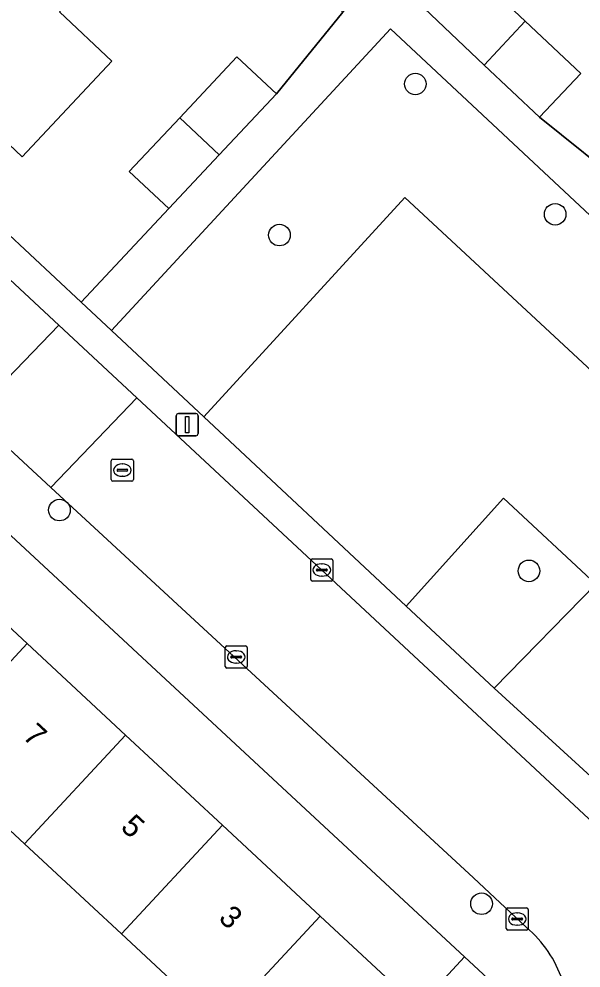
# Model space of a CAD drawing. Extents: x 159217 to 160349, y 381246 to 382172.
# Drawn here: x 159794.16 to 159819.61, y 381597.04 to 381640.02 of the extents above; entities that cross this region are included whole.
import ezdxf

# ---------------------------------------------------------------- set-up
doc = ezdxf.new("R2010")
doc.units = 0
for name, color, linetype in [('IMGEO_Boom', 7, 'Continuous'), ('IMGEO_Erf', 7, 'Continuous'), ('IMGEO_Groenvoorziening', 7, 'Continuous'), ('IMGEO_Kolk', 7, 'Continuous'), ('IMGEO_Lichtmast', 7, 'Continuous'), ('IMGEO_Pand', 7, 'Continuous'), ('IMGEO_Pand_nummerreeks', 7, 'Continuous'), ('IMGEO_Rijbaan_lokaal_open', 7, 'Continuous'), ('IMGEO_Rioolput', 7, 'Continuous'), ('IMGEO_Voetpad_open', 7, 'Continuous')]:
    doc.layers.add(name, color=color, linetype=linetype)

msp = doc.modelspace()

# ---------------------------------------------------------------- linework, layer by layer
at = {"layer": 'IMGEO_Boom'}
for centre in [(159812.109, 381637.076), (159818.442, 381631.175), (159805.956, 381630.234), (159795.992, 381617.781), (159817.255, 381615.027), (159815.108, 381599.955)]:
    msp.add_circle(centre, 0.489, dxfattribs=at)
at = {"layer": 'IMGEO_Erf'}
msp.add_lwpolyline([(159803.656, 381658.338), (159807.515, 381662.454), (159807.241, 381662.71), (159807.449, 381662.932), (159812.834, 381657.884), (159812.651, 381657.689), (159812.448, 381657.879), (159808.564, 381653.736), (159804.32, 381649.211), (159800.254, 381644.874), (159796.153, 381640.501), (159795.998, 381640.336), (159798.369, 381638.113), (159794.311, 381633.784), (159792.204, 381635.759), (159786.767, 381640.857), (159786.941, 381641.042), (159787.205, 381640.794), (159791.245, 381645.103), (159795.346, 381649.477), (159799.412, 381653.813)], close=True, dxfattribs=at)
for points in [[(159780.684, 381642.43), (159796.971, 381627.201), (159800.946, 381631.43), (159799.157, 381633.108), (159801.44, 381635.543), (159804.025, 381638.3), (159805.815, 381636.622), (159808.819, 381640.327), (159806.825, 381642.15), (159809.145, 381644.687), (159811.789, 381647.578), (159813.783, 381645.754), (159811.116, 381642.838), (159810.61, 381642.285), (159812.503, 381640.514), (159814.366, 381642.487), (159817.086, 381639.917), (159819.598, 381637.544), (159817.734, 381635.572), (159821.799, 381632.312)], [(159812.344, 381595.399), (159814.342, 381597.549), (159774.325, 381634.697), (159774.102, 381634.87), (159773.865, 381635.022), (159773.615, 381635.152), (159773.355, 381635.259), (159773.086, 381635.343), (159772.811, 381635.402), (159772.531, 381635.436), (159772.249, 381635.446), (159771.968, 381635.43), (159771.689, 381635.389), (159771.416, 381635.323), (159771.149, 381635.234), (159770.891, 381635.12), (159770.644, 381634.984), (159770.41, 381634.827), (159770.255, 381634.704), (159745.629, 381606.638), (159764.873, 381588.845)], [(159803.227, 381594.477), (159798.802, 381598.589), (159794.41, 381602.671), (159789.957, 381606.81), (159785.693, 381610.772), (159785.453, 381610.514), (159785.255, 381610.698), (159786.948, 381612.519), (159790.351, 381616.181), (159790.548, 381615.997), (159790.268, 381615.695), (159794.532, 381611.733), (159798.985, 381607.593), (159803.377, 381603.512), (159807.802, 381599.4), (159812.029, 381595.471)]]:
    msp.add_lwpolyline(points, dxfattribs=at)
at = {"layer": 'IMGEO_Groenvoorziening'}
for points in [[(159831.37, 381620.522), (159810.981, 381639.573), (159798.344, 381625.917), (159802.529, 381622.003), (159811.633, 381631.939), (159833.028, 381612.068), (159836.458, 381615.77)], [(159811.633, 381631.939), (159802.529, 381622.003), (159811.692, 381613.435), (159816.102, 381618.314), (159820.288, 381614.431), (159815.676, 381609.71), (159820.934, 381604.918), (159825.276, 381609.576), (159828.247, 381606.909), (159833.028, 381612.068)], [(159811.692, 381613.435), (159815.676, 381609.71), (159820.288, 381614.431), (159816.102, 381618.314)]]:
    msp.add_lwpolyline(points, close=True, dxfattribs=at)
msp.add_lwpolyline([(159815.605, 381596.377), (159814.342, 381597.549), (159812.344, 381595.399), (159807.391, 381590.069), (159807.261, 381590.19), (159803.375, 381586.01), (159800.881, 381583.327), (159799.047, 381585.03), (159797.402, 381586.508), (159796.068, 381585.081), (159795.325, 381583.417), (159801.486, 381577.736), (159815.991, 381593.468)], dxfattribs=at)
at = {"layer": 'IMGEO_Kolk'}
for p, q in [((159807.374, 381614.642), (159807.374, 381615.494)), ((159807.449, 381615.568), (159808.301, 381615.568)), ((159808.375, 381615.494), (159808.375, 381614.642)), ((159807.633, 381615.062), (159807.633, 381615.074)), ((159807.676, 381615.111), (159808.074, 381615.111)), ((159807.862, 381615.348), (159807.887, 381615.348)), ((159808.117, 381615.074), (159808.117, 381615.062)), ((159808.071, 381615.025), (159807.673, 381615.025)), ((159807.885, 381614.788), (159807.86, 381614.788)), ((159808.301, 381614.568), (159807.449, 381614.568)), ((159803.573, 381611.63), (159804.425, 381611.63)), ((159803.498, 381610.704), (159803.498, 381611.556)), ((159803.8, 381611.173), (159804.198, 381611.173)), ((159803.986, 381611.41), (159804.011, 381611.41)), ((159804.499, 381611.556), (159804.499, 381610.704)), ((159803.757, 381611.124), (159803.757, 381611.136)), ((159804.195, 381611.087), (159803.797, 381611.087)), ((159804.009, 381610.85), (159803.984, 381610.85)), ((159804.241, 381611.136), (159804.241, 381611.124)), ((159804.425, 381610.63), (159803.573, 381610.63)), ((159816.224, 381598.838), (159816.224, 381599.69)), ((159816.299, 381599.764), (159817.151, 381599.764)), ((159817.225, 381599.69), (159817.225, 381598.838)), ((159816.483, 381599.258), (159816.483, 381599.27)), ((159816.921, 381599.221), (159816.523, 381599.221)), ((159816.526, 381599.307), (159816.924, 381599.307)), ((159816.712, 381599.544), (159816.737, 381599.544)), ((159816.967, 381599.27), (159816.967, 381599.258)), ((159817.151, 381598.764), (159816.299, 381598.764)), ((159816.735, 381598.984), (159816.71, 381598.984))]:
    msp.add_line(p, q, dxfattribs=at)
for points in [[(159807.374, 381614.642), (159807.374, 381615.494)], [(159807.449, 381615.568), (159808.301, 381615.568)], [(159808.375, 381615.494), (159808.375, 381614.642)], [(159808.301, 381614.568), (159807.449, 381614.568)], [(159803.573, 381611.63), (159804.425, 381611.63)], [(159803.498, 381610.704), (159803.498, 381611.556)], [(159804.499, 381611.556), (159804.499, 381610.704)], [(159804.425, 381610.63), (159803.573, 381610.63)], [(159816.224, 381598.838), (159816.224, 381599.69)], [(159816.299, 381599.764), (159817.151, 381599.764)], [(159817.225, 381599.69), (159817.225, 381598.838)], [(159817.151, 381598.764), (159816.299, 381598.764)]]:
    msp.add_lwpolyline(points, dxfattribs=at)
for centre, radius, start, end in [((159807.451, 381615.492), 0.0765, 91.552, 178.448), ((159807.451, 381615.492), 0.0765, 91.552, 178.448), ((159808.299, 381615.492), 0.0765, 1.552, 88.448), ((159808.299, 381615.492), 0.0765, 1.552, 88.448), ((159807.673, 381615.071), 0.0403, 85.8775, 175.7526), ((159807.67, 381615.061), 0.0366, 178.938, 274.7102), ((159808.074, 381615.068), 0.043, 264.8664, 352.4533), ((159808.078, 381615.073), 0.0386, 1.7309, 96.639), ((159807.451, 381614.644), 0.0765, 181.552, 268.448), ((159807.451, 381614.644), 0.0765, 181.552, 268.448), ((159808.299, 381614.644), 0.0765, 271.552, 358.448), ((159808.299, 381614.644), 0.0765, 271.552, 358.448), ((159803.575, 381611.554), 0.0765, 91.552, 178.448), ((159803.575, 381611.554), 0.0765, 91.552, 178.448), ((159804.423, 381611.554), 0.0765, 1.552, 88.448), ((159804.423, 381611.554), 0.0765, 1.552, 88.448), ((159803.797, 381611.133), 0.0403, 85.8775, 175.7526), ((159804.202, 381611.135), 0.0386, 1.7309, 96.639), ((159803.794, 381611.123), 0.0366, 178.938, 274.7102), ((159804.198, 381611.13), 0.043, 264.8664, 352.4533), ((159803.575, 381610.706), 0.0765, 181.552, 268.448), ((159803.575, 381610.706), 0.0765, 181.552, 268.448), ((159804.423, 381610.706), 0.0765, 271.552, 358.448), ((159804.423, 381610.706), 0.0765, 271.552, 358.448), ((159816.301, 381599.688), 0.0765, 91.552, 178.448), ((159816.301, 381599.688), 0.0765, 91.552, 178.448), ((159817.149, 381599.688), 0.0765, 1.552, 88.448), ((159817.149, 381599.688), 0.0765, 1.552, 88.448), ((159816.523, 381599.267), 0.0403, 85.8775, 175.7526), ((159816.52, 381599.257), 0.0366, 178.938, 274.7102), ((159816.924, 381599.264), 0.043, 264.8664, 352.4533), ((159816.928, 381599.269), 0.0386, 1.7309, 96.639), ((159816.301, 381598.84), 0.0765, 181.552, 268.448), ((159816.301, 381598.84), 0.0765, 181.552, 268.448), ((159817.149, 381598.84), 0.0765, 271.552, 358.448), ((159817.149, 381598.84), 0.0765, 271.552, 358.448)]:
    msp.add_arc(centre, radius, start, end, dxfattribs=at)
for centre, major_axis, ratio, start_param, end_param in [((159807.861, 381615.068), (-0.387, 0.002), 0.722429, 4.712389, 7.853982), ((159807.886, 381615.068), (-0.39, 0.002), 0.717154, 1.570796, 4.712389), ((159803.985, 381611.13), (-0.387, 0.002), 0.722429, 4.712389, 7.853982), ((159804.01, 381611.13), (-0.39, 0.002), 0.717154, 1.570796, 4.712389), ((159816.711, 381599.264), (-0.387, 0.002), 0.722429, 4.712389, 7.853982), ((159816.736, 381599.264), (-0.39, 0.002), 0.717154, 1.570796, 4.712389)]:
    msp.add_ellipse(centre, major_axis=major_axis, ratio=ratio, start_param=start_param, end_param=end_param, dxfattribs=at)
at = {"layer": 'IMGEO_Lichtmast'}
for p, q in [((159801.285, 381621.25), (159801.285, 381622.05)), ((159801.285, 381622.05), (159801.285, 381621.25)), ((159801.385, 381622.15), (159802.175, 381622.15)), ((159802.175, 381622.15), (159801.385, 381622.15)), ((159802.275, 381622.05), (159802.275, 381621.25)), ((159802.275, 381621.25), (159802.275, 381622.05)), ((159802.175, 381621.15), (159801.385, 381621.15)), ((159801.385, 381621.15), (159802.175, 381621.15))]:
    msp.add_line(p, q, dxfattribs=at)
msp.add_lwpolyline([(159801.705, 381622.025), (159801.855, 381622.025), (159801.855, 381621.275), (159801.705, 381621.275), (159801.705, 381622.025)], dxfattribs=at)
for centre, start, end in [((159801.385, 381622.05), 90, 180), ((159801.385, 381622.05), 90, 180), ((159802.175, 381622.05), 0, 90), ((159802.175, 381622.05), 360, 90), ((159801.385, 381621.25), 180, 270), ((159801.385, 381621.25), 180, 270), ((159802.175, 381621.25), 270, 0), ((159802.175, 381621.25), 270, 0)]:
    msp.add_arc(centre, 0.1, start, end, dxfattribs=at)
at = {"layer": 'IMGEO_Pand'}
for points in [[(159795.998, 381640.336), (159796.153, 381640.501), (159791.245, 381645.103), (159787.205, 381640.794), (159786.941, 381641.042), (159786.767, 381640.857), (159792.204, 381635.759), (159794.311, 381633.784), (159798.369, 381638.113)], [(159817.086, 381639.917), (159814.366, 381642.487), (159812.503, 381640.514), (159815.234, 381637.934)], [(159817.086, 381639.917), (159815.234, 381637.934), (159817.734, 381635.572), (159819.598, 381637.544)], [(159801.44, 381635.543), (159803.23, 381633.865), (159805.815, 381636.622), (159804.025, 381638.3)], [(159801.44, 381635.543), (159799.157, 381633.108), (159800.946, 381631.43), (159803.23, 381633.865)], [(159794.532, 381611.733), (159790.268, 381615.695), (159790.548, 381615.997), (159790.351, 381616.181), (159786.948, 381612.519), (159785.255, 381610.698), (159785.453, 381610.514), (159785.693, 381610.772), (159789.957, 381606.81)], [(159794.41, 381602.671), (159798.985, 381607.593), (159794.532, 381611.733), (159789.957, 381606.81)], [(159803.377, 381603.512), (159798.985, 381607.593), (159794.41, 381602.671), (159798.802, 381598.589)], [(159803.377, 381603.512), (159798.802, 381598.589), (159803.227, 381594.477), (159807.802, 381599.4)], [(159812.344, 381595.399), (159812.138, 381595.589), (159812.029, 381595.471), (159807.802, 381599.4), (159803.227, 381594.477), (159803.804, 381593.941), (159807.467, 381590.538), (159807.198, 381590.248), (159807.261, 381590.19), (159807.391, 381590.069)]]:
    msp.add_lwpolyline(points, close=True, dxfattribs=at)
at = {"layer": 'IMGEO_Rijbaan_lokaal_open'}
for points in [[(159776.131, 381645.821), (159770.319, 381639.348), (159770.698, 381639.358), (159771.353, 381639.33), (159772.003, 381639.243), (159772.643, 381639.098), (159773.268, 381638.897), (159773.871, 381638.641), (159774.45, 381638.332), (159776.205, 381636.697), (159779.881, 381633.337), (159792.042, 381622.099), (159795.967, 381626.155), (159793.749, 381628.22), (159781.571, 381639.325), (159779.33, 381641.41), (159777.705, 381642.919)], [(159799.503, 381622.862), (159795.604, 381618.808), (159814.742, 381601.123), (159817.14, 381598.878)], [(159820.849, 381602.985), (159799.503, 381622.862)]]:
    msp.add_lwpolyline(points, dxfattribs=at)
msp.add_lwpolyline([(159792.042, 381622.099), (159795.604, 381618.808), (159799.503, 381622.862), (159795.967, 381626.155)], close=True, dxfattribs=at)
msp.add_arc((159813.764, 381594.834), 5.268, 18.2385, 50.1405, dxfattribs=at)
at = {"layer": 'IMGEO_Rioolput'}
for p, q in [((159798.341, 381619.164), (159798.341, 381620.016)), ((159798.416, 381620.09), (159799.268, 381620.09)), ((159798.829, 381619.87), (159798.854, 381619.87)), ((159799.342, 381620.016), (159799.342, 381619.164)), ((159798.6, 381619.584), (159798.6, 381619.596)), ((159799.038, 381619.547), (159798.64, 381619.547)), ((159798.643, 381619.633), (159799.041, 381619.633)), ((159799.084, 381619.596), (159799.084, 381619.584)), ((159799.268, 381619.09), (159798.416, 381619.09)), ((159798.852, 381619.31), (159798.827, 381619.31))]:
    msp.add_line(p, q, dxfattribs=at)
for points in [[(159798.341, 381619.164), (159798.341, 381620.016)], [(159798.416, 381620.09), (159799.268, 381620.09)], [(159799.342, 381620.016), (159799.342, 381619.164)], [(159799.268, 381619.09), (159798.416, 381619.09)]]:
    msp.add_lwpolyline(points, dxfattribs=at)
for centre, radius, start, end in [((159798.418, 381620.014), 0.0765, 91.552, 178.448), ((159798.418, 381620.014), 0.0765, 91.552, 178.448), ((159799.266, 381620.014), 0.0765, 1.552, 88.448), ((159799.266, 381620.014), 0.0765, 1.552, 88.448), ((159798.64, 381619.593), 0.0403, 85.8775, 175.7526), ((159798.637, 381619.583), 0.0366, 178.938, 274.7102), ((159799.041, 381619.59), 0.043, 264.8664, 352.4533), ((159799.045, 381619.595), 0.0386, 1.7309, 96.639), ((159798.418, 381619.166), 0.0765, 181.552, 268.448), ((159798.418, 381619.166), 0.0765, 181.552, 268.448), ((159799.266, 381619.166), 0.0765, 271.552, 358.448), ((159799.266, 381619.166), 0.0765, 271.552, 358.448)]:
    msp.add_arc(centre, radius, start, end, dxfattribs=at)
for centre, major_axis, ratio, start_param, end_param in [((159798.828, 381619.59), (-0.387, 0.002), 0.722429, 4.712389, 7.853982), ((159798.853, 381619.59), (-0.39, 0.002), 0.717154, 1.570796, 4.712389)]:
    msp.add_ellipse(centre, major_axis=major_axis, ratio=ratio, start_param=start_param, end_param=end_param, dxfattribs=at)
at = {"layer": 'IMGEO_Voetpad_open'}
for points in [[(159780.479, 381646.24), (159777.705, 381642.919), (159779.33, 381641.41), (159781.571, 381639.325), (159793.749, 381628.22), (159795.967, 381626.155), (159799.503, 381622.862), (159820.849, 381602.985), (159821.231, 381602.635), (159821.643, 381602.321), (159822.082, 381602.045), (159822.543, 381601.81), (159823.024, 381601.616), (159823.52, 381601.466), (159824.027, 381601.361), (159825.907, 381604.369)], [(159802.529, 381622.003), (159798.344, 381625.917), (159796.971, 381627.201), (159780.684, 381642.43)], [(159774.325, 381634.697), (159814.342, 381597.549), (159815.605, 381596.377)], [(159795.604, 381618.808), (159792.042, 381622.099)], [(159822.03, 381603.951), (159820.934, 381604.918), (159815.676, 381609.71), (159811.692, 381613.435), (159802.529, 381622.003)], [(159817.14, 381598.878), (159814.742, 381601.123), (159795.604, 381618.808)]]:
    msp.add_lwpolyline(points, dxfattribs=at)
msp.add_lwpolyline([(159827.134, 381627.623), (159826.853, 381627.3), (159824.175, 381629.786), (159821.645, 381632.135), (159821.799, 381632.312), (159817.734, 381635.572), (159815.234, 381637.934), (159812.503, 381640.514), (159810.61, 381642.285), (159808.819, 381640.327), (159805.815, 381636.622), (159803.23, 381633.865), (159800.946, 381631.43), (159796.971, 381627.201), (159798.344, 381625.917), (159810.981, 381639.573), (159831.37, 381620.522), (159836.458, 381615.77), (159837.909, 381617.335), (159833.376, 381621.566), (159831.5, 381623.317)], close=True, dxfattribs=at)
msp.add_arc((159813.764, 381594.834), 5.268, 18.2385, 50.1405, dxfattribs=at)

# ---------------------------------------------------------------- texts
at = {"layer": 'IMGEO_Pand_nummerreeks'}
for s, p in [('7', (159794.285, 381607.485)), ('5', (159798.718, 381603.365)), ('3', (159803.151, 381599.246))]:
    msp.add_text(s, height=1, rotation=317.0966, dxfattribs=at).set_placement(p)

doc.saveas('drawing.dxf')
